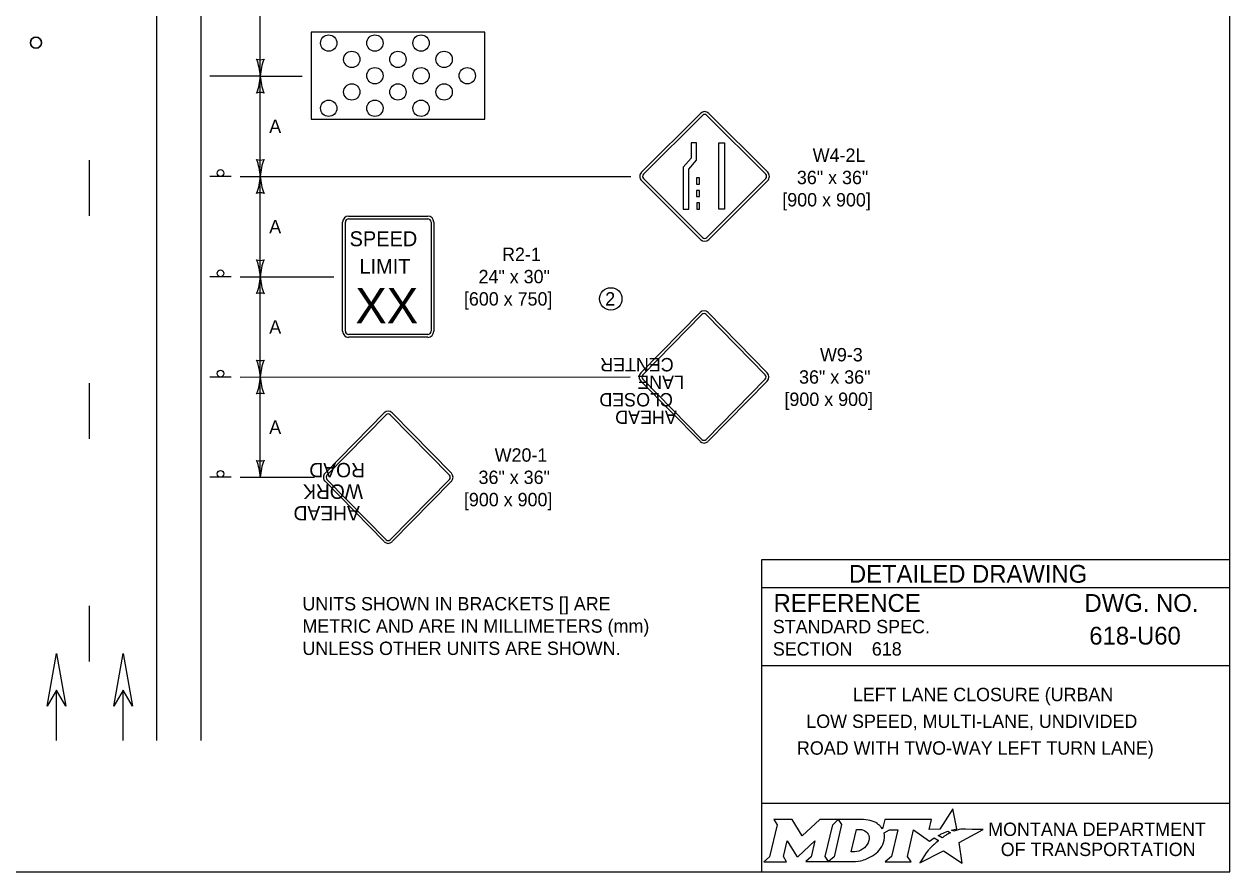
# Model space of a CAD drawing. Extents: x 49991.4 to 50021, y 49987.6 to 50011.4.
# Drawn here: x 50003.21 to 50008.61, y 50000.06 to 50003.87 of the extents above; entities that cross this region are included whole.
import ezdxf

# ---------------------------------------------------------------- set-up
doc = ezdxf.new("R2010")
doc.units = 0
for name, color, linetype in [('Level 1', 7, 'Continuous'), ('Level 2', 7, 'Continuous'), ('Level 25', 7, 'Continuous'), ('Level 3', 7, 'Continuous'), ('S_BOT_RW_TTL_Sheet_No_DF', 7, 'Continuous')]:
    doc.layers.add(name, color=color, linetype=linetype)

msp = doc.modelspace()

# ---------------------------------------------------------------- linework, layer by layer
at = {"layer": 'Level 1'}
for p, q in [((50003.8002, 50009.1708), (50003.8002, 50000.6526)), ((50004.0002, 50009.1708), (50004.0002, 50000.6526)), ((50003.5003, 50003.0059), (50003.5003, 50003.2559)), ((50004.1362, 50003.1829), (50004.0402, 50003.1829)), ((50004.6627, 50003.0049), (50005.0172, 50003.0049)), ((50004.9262, 50003.003), (50004.9262, 50003.003)), ((50004.6355, 50002.4881), (50004.6355, 50002.9777)), ((50004.6479, 50002.4881), (50004.6479, 50002.9777)), ((50004.6627, 50002.9925), (50005.0172, 50002.9925)), ((50005.032, 50002.9777), (50005.032, 50002.4881)), ((50005.0444, 50002.9777), (50005.0444, 50002.4881)), ((50004.1362, 50002.7329), (50004.0402, 50002.7329)), ((50005.9731, 50002.3012), (50006.2383, 50002.5719)), ((50006.2746, 50002.5719), (50006.5398, 50002.3012)), ((50005.982, 50002.2925), (50006.2472, 50002.5632)), ((50006.2657, 50002.5632), (50006.5309, 50002.2925)), ((50005.0172, 50002.4734), (50004.6627, 50002.4734)), ((50005.0172, 50002.461), (50004.6627, 50002.461)), ((50003.5003, 50002.0059), (50003.5003, 50002.2559)), ((50003.5003, 50002.0059), (50003.5003, 50002.2559)), ((50004.1362, 50002.2829), (50004.0402, 50002.2829)), ((50006.2383, 50001.9943), (50005.9731, 50002.2649)), ((50006.2472, 50002.0029), (50005.982, 50002.2736)), ((50006.5309, 50002.2736), (50006.2657, 50002.0029)), ((50006.5398, 50002.2649), (50006.2746, 50001.9943)), ((50004.5566, 50001.8511), (50004.8218, 50002.1218)), ((50004.5655, 50001.8424), (50004.8307, 50002.1131)), ((50004.8492, 50002.1131), (50005.1144, 50001.8424)), ((50004.8581, 50002.1218), (50005.1233, 50001.8511)), ((50004.1362, 50001.8329), (50004.0402, 50001.8329)), ((50004.8218, 50001.5442), (50004.5566, 50001.8149)), ((50004.8307, 50001.5528), (50004.5655, 50001.8235)), ((50005.1144, 50001.8235), (50004.8492, 50001.5528)), ((50005.1233, 50001.8149), (50004.8581, 50001.5442)), ((50003.5003, 50001.0059), (50003.5003, 50001.2559)), ((50003.5003, 50001.0059), (50003.5003, 50001.2559)), ((50003.3518, 50000.6526), (50003.3518, 50000.8785)), ((50003.352, 50000.6526), (50003.352, 50000.8785)), ((50003.651, 50000.6526), (50003.651, 50000.8785)), ((50003.6512, 50000.6526), (50003.6512, 50000.8785))]:
    msp.add_line(p, q, dxfattribs=at)
for points in [[(50008.6146, 50011.2628), (50000.3356, 50011.2628), (50000.3356, 50000.0624), (50008.6146, 50000.0624)], [(50005.2735, 50003.8297), (50004.4938, 50003.8297), (50004.4938, 50003.4397), (50005.2735, 50003.4397)], [(50005.2735, 50003.8297), (50004.4938, 50003.8297), (50004.4938, 50003.4397), (50005.2735, 50003.4397)], [(50003.31, 50000.8062), (50003.3518, 50001.0427), (50003.3936, 50000.8062), (50003.3518, 50000.8784)], [(50003.6092, 50000.8062), (50003.651, 50001.0427), (50003.6928, 50000.8062), (50003.651, 50000.8784)]]:
    msp.add_lwpolyline(points, close=True, dxfattribs=at)
for centre, radius in [((50004.5731, 50003.7811), 0.0366), ((50004.5731, 50003.7811), 0.0366), ((50004.7803, 50003.7811), 0.0366), ((50004.7803, 50003.7811), 0.0366), ((50004.9874, 50003.7811), 0.0366), ((50004.9874, 50003.7811), 0.0366), ((50003.2602, 50003.7829), 0.025), ((50004.6767, 50003.708), 0.0366), ((50004.6767, 50003.708), 0.0366), ((50004.8838, 50003.708), 0.0366), ((50004.8838, 50003.708), 0.0366), ((50005.0909, 50003.708), 0.0366), ((50005.0909, 50003.708), 0.0366), ((50004.7803, 50003.6349), 0.0366), ((50004.7803, 50003.6349), 0.0366), ((50004.9874, 50003.6349), 0.0366), ((50004.9874, 50003.6349), 0.0366), ((50005.1945, 50003.6349), 0.0366), ((50005.1945, 50003.6349), 0.0366), ((50004.6767, 50003.5618), 0.0366), ((50004.6767, 50003.5618), 0.0366), ((50004.8838, 50003.5618), 0.0366), ((50004.8838, 50003.5618), 0.0366), ((50005.0909, 50003.5618), 0.0366), ((50005.0909, 50003.5618), 0.0366), ((50004.5731, 50003.4887), 0.0366), ((50004.5731, 50003.4887), 0.0366), ((50004.7803, 50003.4887), 0.0366), ((50004.7803, 50003.4887), 0.0366), ((50004.9874, 50003.4887), 0.0366), ((50004.9874, 50003.4887), 0.0366), ((50004.0881, 50003.1981), 0.0152), ((50004.0881, 50002.7481), 0.0152), ((50004.0881, 50002.2981), 0.0152), ((50004.0881, 50001.8481), 0.0152)]:
    msp.add_circle(centre, radius, dxfattribs=at)
for centre, radius, start, end in [((50003.2602, 50003.7829), 0.025, 0, 180), ((50003.2602, 50003.7829), 0.025, 180, 0), ((50004.6627, 50002.9777), 0.0272, 90, 180), ((50005.0172, 50002.9777), 0.0272, 0, 90), ((50004.6627, 50002.9777), 0.0148, 90, 180), ((50005.0172, 50002.9777), 0.0148, 0, 90), ((50004.6627, 50002.4881), 0.0272, 180, 270), ((50004.6627, 50002.4881), 0.0148, 180, 270), ((50005.0172, 50002.4881), 0.0148, 270, 360), ((50005.0172, 50002.4881), 0.0272, 270, 360)]:
    msp.add_arc(centre, radius, start, end, dxfattribs=at)
for centre, major_axis, ratio, start_param, end_param in [((50006.2564, 50002.5537), (0, 0.0258), 0.98963, 5.497787, 7.068583), ((50006.2564, 50002.5537), (0, 0.0134), 0.98, 5.497787, 7.068583), ((50005.9912, 50002.283), (0, 0.0258), 0.98963, 0.785394, 2.356194), ((50006.5217, 50002.283), (0, 0.0258), 0.98963, 3.926991, 5.497787), ((50005.9912, 50002.283), (0, 0.0134), 0.98, 0.785394, 2.356194), ((50006.5217, 50002.283), (0, 0.0134), 0.98, 3.926991, 5.497787), ((50004.8399, 50002.1036), (0, 0.0258), 0.98963, 5.497787, 7.068583), ((50004.8399, 50002.1036), (0, 0.0134), 0.98, 5.497787, 7.068583), ((50006.2564, 50002.0124), (0, -0.0258), 0.98963, 5.497795, 7.068583), ((50006.2564, 50002.0124), (0, -0.0134), 0.98, 5.497795, 7.068583), ((50004.5747, 50001.8329), (0, 0.0258), 0.98963, 0.785394, 2.356194), ((50004.5747, 50001.8329), (0, 0.0134), 0.98, 0.785394, 2.356194), ((50005.1052, 50001.8329), (0, 0.0134), 0.98, 3.926991, 5.497787), ((50005.1052, 50001.8329), (0, 0.0258), 0.98963, 3.926991, 5.497787), ((50004.8399, 50001.5623), (0, -0.0258), 0.98963, 5.497795, 7.068583), ((50004.8399, 50001.5623), (0, -0.0134), 0.98, 5.497795, 7.068583)]:
    msp.add_ellipse(centre, major_axis=major_axis, ratio=ratio, start_param=start_param, end_param=end_param, dxfattribs=at)
at = {"layer": 'Level 2'}
for p, q in [((50008.6146, 50001.4624), (50006.5146, 50001.4624)), ((50006.5146, 50001.4624), (50006.5146, 50000.0624)), ((50008.6146, 50001.3374), (50006.5146, 50001.3374)), ((50008.2507, 50001.1223), (50008.2507, 50001.1223)), ((50007.0089, 50001.0629), (50007.0089, 50001.0629)), ((50008.6146, 50000.9874), (50006.5146, 50000.9874)), ((50007.5646, 50000.7383), (50007.5646, 50000.7383)), ((50008.6146, 50000.3693), (50006.5146, 50000.3693))]:
    msp.add_line(p, q, dxfattribs=at)
for points in [[(50006.5701, 50000.2974), (50006.5842, 50000.274), (50006.5507, 50000.1307), (50006.525, 50000.1082), (50006.6266, 50000.1082), (50006.6131, 50000.131), (50006.6293, 50000.2011), (50006.673, 50000.1321), (50006.6783, 50000.1321), (50006.7534, 50000.2016), (50006.737, 50000.1305), (50006.7123, 50000.1085), (50006.8139, 50000.1085), (50006.8001, 50000.1318), (50006.8333, 50000.2742)], [(50006.8333, 50000.2742), (50006.8586, 50000.2974), (50006.7762, 50000.2974), (50006.6966, 50000.2244), (50006.6521, 50000.2971), (50006.5701, 50000.2974)], [(50006.9722, 50000.2974), (50006.8586, 50000.2974), (50006.8733, 50000.2745), (50006.8394, 50000.1307), (50006.8139, 50000.1085), (50006.9245, 50000.1085)], [(50007.3771, 50000.2447), (50007.3668, 50000.2503), (50007.3784, 50000.2531), (50007.39, 50000.2551), (50007.3726, 50000.3452), (50007.3131, 50000.2539), (50007.2658, 50000.2532), (50007.2761, 50000.2973), (50007.0669, 50000.2974), (50007.0568, 50000.2549), (50007.051, 50000.2632)], [(50006.9962, 50000.2107), (50006.995, 50000.2026), (50006.9918, 50000.1933), (50006.9876, 50000.1851), (50006.982, 50000.1776), (50006.9755, 50000.1707), (50006.9676, 50000.1644), (50006.9593, 50000.1597), (50006.9502, 50000.1558), (50006.9411, 50000.1535), (50006.9319, 50000.1526), (50006.916, 50000.1526), (50006.9396, 50000.2526), (50006.9556, 50000.2526), (50006.9632, 50000.252), (50006.9708, 50000.2501), (50006.9774, 50000.2471), (50006.9835, 50000.2429), (50006.9883, 50000.2379), (50006.992, 50000.2319), (50006.9947, 50000.2257), (50006.9963, 50000.2183), (50006.9963, 50000.2153), (50006.9962, 50000.2107)], [(50007.0636, 50000.2383), (50007.0882, 50000.2514), (50007.1251, 50000.2514), (50007.0965, 50000.1309), (50007.069, 50000.1082), (50007.1852, 50000.1082), (50007.1682, 50000.1311), (50007.1964, 50000.2513), (50007.2677, 50000.1996), (50007.2888, 50000.2147), (50007.3085, 50000.2038)], [(50007.2527, 50000.1479), (50007.2374, 50000.1235), (50007.2327, 50000.116), (50007.2269, 50000.1074), (50007.2246, 50000.1031), (50007.3299, 50000.1562), (50007.4138, 50000.1011), (50007.4007, 50000.1938), (50007.5076, 50000.2522), (50007.4583, 50000.253), (50007.4282, 50000.2534), (50007.4074, 50000.2537), (50007.4006, 50000.2522), (50007.3957, 50000.251), (50007.3873, 50000.2487), (50007.3771, 50000.2447)], [(50007.3267, 50000.2171), (50007.3243, 50000.2154), (50007.306, 50000.225), (50007.3163, 50000.2307), (50007.3204, 50000.2329), (50007.329, 50000.2369), (50007.3347, 50000.2395), (50007.3426, 50000.2425), (50007.3499, 50000.2452), (50007.3617, 50000.2378), (50007.3577, 50000.2357), (50007.3531, 50000.2332), (50007.3489, 50000.231), (50007.3439, 50000.2281), (50007.342, 50000.227), (50007.3393, 50000.2254), (50007.3368, 50000.224), (50007.3345, 50000.2224), (50007.3319, 50000.2206), (50007.3292, 50000.2188), (50007.3267, 50000.2171)], [(50006.9702, 50000.1158), (50006.9786, 50000.1184), (50006.9916, 50000.1238), (50007.012, 50000.1348)], [(50007.2666, 50000.164), (50007.2666, 50000.164)]]:
    msp.add_lwpolyline(points, dxfattribs=at)
msp.add_circle((50005.8383, 50002.6334), 0.0501, dxfattribs=at)
for centre, radius, start, end in [((50006.9513, 50000.2363), 0.1183, 300.9103, 339.1383), ((50006.9953, 50000.219), 0.0709, 339.5329, 15.8582)]:
    msp.add_arc(centre, radius, start, end, dxfattribs=at)
for centre, major_axis, ratio, start_param, end_param in [((50006.9701, 50000.25), (0.0834, -0.0037), 0.568097, 0.61298, 1.570796), ((50007.0257, 50000.2573), (0.0361, -0.0295), 0.469099, 1.225588, 1.570796), ((50007.2974, 50000.1941), (-0.0112, -0.0097), 0.021651, 3.157348, 6.283185), ((50007.2597, 50000.1559), (-0.00694, -0.00806), 0.008222, 0, 3.137361), ((50007.2764, 50000.1742), (-0.0098, -0.0102), 0.016458, 3.141593, 6.279097), ((50006.9248, 50000.2568), (0, 0.1484), 0.987302, 3.139398, 3.456847)]:
    msp.add_ellipse(centre, major_axis=major_axis, ratio=ratio, start_param=start_param, end_param=end_param, dxfattribs=at)
at = {"layer": 'Level 25'}
for p, q in [((50006.2401, 50003.4658), (50005.9761, 50003.2018)), ((50005.985, 50003.1929), (50006.249, 50003.4569)), ((50006.2689, 50003.4569), (50006.533, 50003.1929)), ((50006.2689, 50003.4569), (50006.2689, 50003.4569)), ((50006.5419, 50003.2018), (50006.2778, 50003.4658)), ((50006.3229, 50003.0356), (50006.3229, 50003.3333)), ((50006.3229, 50003.3333), (50006.3475, 50003.3333)), ((50006.3475, 50003.3333), (50006.3475, 50003.0356)), ((50005.9761, 50003.1641), (50006.2401, 50002.9)), ((50006.249, 50002.9089), (50005.985, 50003.173)), ((50006.533, 50003.173), (50006.2689, 50002.9089)), ((50006.2778, 50002.9), (50006.5419, 50003.1641)), ((50006.3475, 50003.0356), (50006.3229, 50003.0356))]:
    msp.add_line(p, q, dxfattribs=at)
msp.add_lwpolyline([(50006.3066, 50003.017), (50006.3064, 50003.0171)], dxfattribs=at)
for centre, radius, start, end in [((50006.259, 50003.447), 0.0267, 45.0001, 134.9999), ((50006.259, 50003.447), 0.0141, 45.0001, 134.9999), ((50005.9949, 50003.1829), 0.0267, 134.9999, 225.0001), ((50005.9949, 50003.1829), 0.0141, 134.9999, 225.0001), ((50006.523, 50003.1829), 0.0141, 314.9999, 45.0001), ((50006.523, 50003.1829), 0.0267, 314.9999, 45.0001), ((50006.259, 50002.9189), 0.0267, 225.0001, 314.9999), ((50006.259, 50002.9189), 0.0141, 225.0001, 314.9999)]:
    msp.add_arc(centre, radius, start, end, dxfattribs=at)
at = {"layer": 'Level 3'}
for p, q in [((50004.2665, 50003.6329), (50004.2665, 50004.2329)), ((50004.2665, 50003.6329), (50004.0402, 50003.6329)), ((50004.2665, 50003.1829), (50004.2665, 50003.6329)), ((50004.2665, 50003.6329), (50004.3865, 50003.6329)), ((50004.3865, 50003.6329), (50004.4539, 50003.6329)), ((50004.1762, 50003.1829), (50005.9282, 50003.1829)), ((50004.2665, 50002.7329), (50004.2665, 50003.1829)), ((50004.1762, 50002.7329), (50004.5955, 50002.7329)), ((50004.2665, 50002.2829), (50004.2665, 50002.7329)), ((50004.1762, 50002.2829), (50005.9257, 50002.283)), ((50004.2665, 50001.8329), (50004.2665, 50002.2829)), ((50004.1762, 50001.8329), (50004.5092, 50001.8329))]:
    msp.add_line(p, q, dxfattribs=at)
for centre, radius, start, end in [((50004.2665, 50003.7611), 0.0548, 252.1388, 287.8612), ((50004.0338, 50003.6214), 0.233, 2.8273, 22.0772), ((50004.4886, 50003.6238), 0.2223, 157.456, 177.6395), ((50004.0444, 50003.6421), 0.2223, 337.456, 357.6395), ((50004.0444, 50003.6421), 0.2223, 337.456, 357.6395), ((50004.4992, 50003.6444), 0.233, 182.8273, 202.0772), ((50004.4992, 50003.6444), 0.233, 182.8273, 202.0772), ((50004.2665, 50003.5047), 0.0548, 72.1388, 107.8612), ((50004.2665, 50003.5047), 0.0548, 72.1388, 107.8612), ((50004.2665, 50003.3111), 0.0548, 252.1388, 287.8612), ((50004.0338, 50003.1714), 0.233, 2.8273, 22.0772), ((50004.4886, 50003.1738), 0.2223, 157.456, 177.6395), ((50004.0444, 50003.1921), 0.2223, 337.456, 357.6395), ((50004.4992, 50003.1944), 0.233, 182.8273, 202.0772), ((50004.2665, 50003.0547), 0.0548, 72.1388, 107.8612), ((50004.2665, 50002.8611), 0.0548, 252.1388, 287.8612), ((50004.0338, 50002.7214), 0.233, 2.8273, 22.0772), ((50004.4886, 50002.7238), 0.2223, 157.456, 177.6395), ((50004.0444, 50002.7421), 0.2223, 337.456, 357.6395), ((50004.4992, 50002.7444), 0.233, 182.8273, 202.0772), ((50004.2665, 50002.6047), 0.0548, 72.1388, 107.8612), ((50004.2665, 50002.4111), 0.0548, 252.1388, 287.8612), ((50004.0338, 50002.2714), 0.233, 2.8273, 22.0772), ((50004.4886, 50002.2738), 0.2223, 157.456, 177.6395), ((50004.0444, 50002.2921), 0.2223, 337.456, 357.6395), ((50004.4992, 50002.2944), 0.233, 182.8273, 202.0772), ((50004.2665, 50002.1547), 0.0548, 72.1388, 107.8612), ((50004.2665, 50001.9611), 0.0548, 252.1388, 287.8612), ((50004.0338, 50001.8214), 0.233, 2.8273, 22.0772), ((50004.4886, 50001.8238), 0.2223, 157.456, 177.6395)]:
    msp.add_arc(centre, radius, start, end, dxfattribs=at)
at = {"layer": 'S_BOT_RW_TTL_Sheet_No_DF'}
for p, q in [((50006.2233, 50003.3333), (50006.1986, 50003.3333)), ((50006.1986, 50003.3333), (50006.1986, 50003.2655)), ((50006.2233, 50003.2563), (50006.2233, 50003.3333)), ((50006.1986, 50003.2655), (50006.1633, 50003.2245)), ((50006.1633, 50003.2245), (50006.1633, 50003.0356)), ((50006.188, 50003.2153), (50006.2233, 50003.2563)), ((50006.188, 50003.0356), (50006.188, 50003.2153)), ((50006.2362, 50003.1769), (50006.2231, 50003.1769)), ((50006.2231, 50003.1769), (50006.2231, 50003.1486)), ((50006.2362, 50003.1486), (50006.2362, 50003.1769)), ((50006.2231, 50003.1486), (50006.2362, 50003.1486)), ((50006.2362, 50003.1203), (50006.2231, 50003.1203)), ((50006.2231, 50003.1203), (50006.2231, 50003.0921)), ((50006.2362, 50003.0921), (50006.2362, 50003.1203)), ((50006.2231, 50003.0921), (50006.2362, 50003.0921)), ((50006.2366, 50003.0638), (50006.2235, 50003.0638)), ((50006.2235, 50003.0638), (50006.2235, 50003.0356)), ((50006.2366, 50003.0356), (50006.2366, 50003.0638)), ((50006.1633, 50003.0356), (50006.188, 50003.0356)), ((50006.2235, 50003.0356), (50006.2366, 50003.0356))]:
    msp.add_line(p, q, dxfattribs=at)

# ---------------------------------------------------------------- texts
at = {"layer": 'Level 1'}
for s, height, p in [('SPEED', 0.06696, (50004.6668, 50002.8697)), ('LIMIT', 0.06696, (50004.7111, 50002.7459)), ('XX', 0.15775, (50004.6928, 50002.5239))]:
    msp.add_text(s, height=height, dxfattribs=at).set_placement(p)
for s, height, p in [('CENTER', 0.06, (50006.1203, 50002.3682)), ('LANE', 0.06, (50006.1664, 50002.2896)), ('CLOSED', 0.06, (50006.117, 50002.2109)), ('AHEAD', 0.06, (50006.1344, 50002.1323)), ('ROAD', 0.06453, (50004.7358, 50001.8975)), ('WORK', 0.06453, (50004.7267, 50001.8007)), ('AHEAD', 0.06453, (50004.7129, 50001.7039))]:
    msp.add_text(s, height=height, rotation=180, dxfattribs=at).set_placement(p)
at = {"layer": 'Level 2'}
for p in [(50004.3065, 50003.3779), (50004.3065, 50002.9279), (50004.3065, 50002.4779), (50004.3065, 50002.0279)]:
    msp.add_text('A', height=0.06, rotation=360, dxfattribs=at).set_placement(p)
for s, height, p in [('W4-2L', 0.06, (50006.7437, 50003.2482)), ('36" x 36"', 0.06, (50006.6728, 50003.1482)), ('[900 x 900]', 0.06, (50006.6073, 50003.0482)), ('R2-1', 0.06, (50005.3506, 50002.8034)), ('24" x 30"', 0.06, (50005.2451, 50002.7034)), ('[600 x 750]', 0.06, (50005.1795, 50002.6034)), ('2', 0.06, (50005.8132, 50002.6034)), ('W9-3', 0.06, (50006.7764, 50002.353)), ('36" x 36"', 0.06, (50006.6826, 50002.253)), ('[900 x 900]', 0.06, (50006.617, 50002.153)), ('W20-1', 0.06, (50005.3174, 50001.9029)), ('36" x 36"', 0.06, (50005.2451, 50001.8029)), ('[900 x 900]', 0.06, (50005.1795, 50001.7029)), ('DETAILED DRAWING', 0.0799, (50006.9063, 50001.3599)), ('UNITS SHOWN IN BRACKETS [] ARE ', 0.06, (50004.4553, 50001.2356)), ('REFERENCE', 0.08, (50006.5682, 50001.229)), ('DWG. NO.', 0.08, (50007.9624, 50001.229)), ('METRIC AND ARE IN MILLIMETERS (mm) ', 0.06, (50004.4553, 50001.1356)), ('STANDARD SPEC.', 0.06, (50006.5649, 50001.133)), ('618-U60', 0.08, (50007.9841, 50001.0823)), ('UNLESS OTHER UNITS ARE SHOWN.', 0.06, (50004.4553, 50001.0356)), ('SECTION', 0.06, (50006.5649, 50001.033)), ('618', 0.06, (50007.0089, 50001.0329)), ('LEFT LANE CLOSURE (URBAN', 0.06, (50006.9236, 50000.8283)), ('LOW SPEED, MULTI-LANE, UNDIVIDED', 0.06, (50006.715, 50000.7083)), ('ROAD WITH TWO-WAY LEFT TURN LANE)', 0.06, (50006.673, 50000.5883)), ('MONTANA DEPARTMENT', 0.06, (50007.5308, 50000.2236)), ('OF TRANSPORTATION', 0.06, (50007.587, 50000.1336))]:
    msp.add_text(s, height=height, dxfattribs=at).set_placement(p)

doc.saveas('drawing.dxf')
